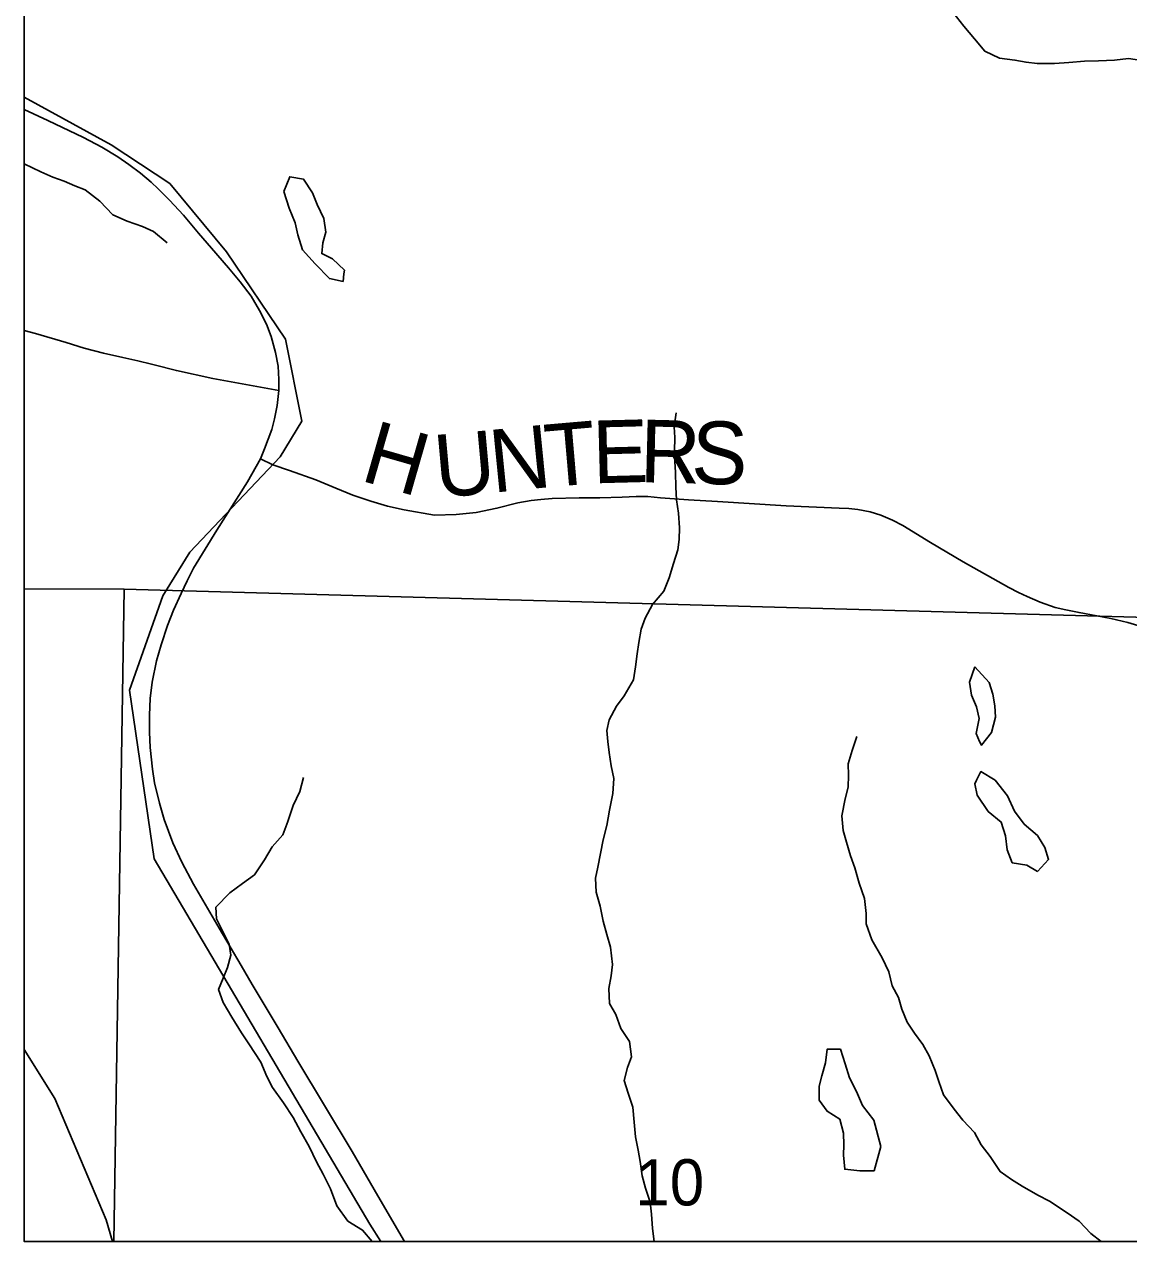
# Model space of a CAD drawing. Extents: x 0 to 34, y 0 to 22.
# Drawn here: x 1.631 to 2.631, y 14.573 to 15.676 of the extents above; entities that cross this region are included whole.
import ezdxf

# ---------------------------------------------------------------- set-up
doc = ezdxf.new("R2010")
doc.units = 0
for name, color, linetype in [('GM_X_Corporation', 7, 'Continuous'), ('GM_X_County_Road', 7, 'Continuous'), ('GM_X_Minor_Lake', 7, 'Continuous'), ('GM_X_Minor_River', 7, 'Continuous'), ('GM_X_Rail_Line', 7, 'Continuous'), ('GM_X_Section_Text', 7, 'Continuous'), ('GM_X_State_Route', 7, 'Continuous'), ('GM_X_Township_Road', 7, 'Continuous'), ('GM_X_Township_Road_Text', 7, 'Continuous'), ('SH_Text', 7, 'Continuous')]:
    doc.layers.add(name, color=color, linetype=linetype)

msp = doc.modelspace()

# ---------------------------------------------------------------- linework, layer by layer
at = {"layer": 'GM_X_Corporation'}
msp.add_lwpolyline([(4.1576, 16.1007), (3.7652, 16.1115), (2.3935, 16.1523), (2.3716, 16.1532), (1.6311, 16.1731), (1.6311, 14.5734), (8.4311, 14.5734)], dxfattribs=at)
for points in [[(1.6311, 16.1731), (1.6311, 14.5734), (3.7221, 14.5734), (3.7347, 15.1105), (3.7348, 15.1121), (3.7459, 15.4785), (3.7461, 15.4826), (3.7495, 15.5967), (3.7652, 16.1115), (2.3935, 16.1523), (2.3716, 16.1532)], [(1.6311, 15.1646), (1.6311, 14.5734), (1.7122, 14.5734), (1.7214, 15.1643)], [(1.7122, 14.5734), (2.7191, 14.5734), (2.725, 15.1366), (1.7214, 15.1643)]]:
    msp.add_lwpolyline(points, close=True, dxfattribs=at)
at = {"layer": 'GM_X_County_Road'}
msp.add_lwpolyline([(1.711, 14.5734), (1.7053, 14.5933), (1.6588, 14.7031), (1.6311, 14.7473)], dxfattribs=at)
at = {"layer": 'GM_X_Minor_Lake'}
for points in [[(1.9205, 15.4498), (1.9209, 15.4533), (1.9103, 15.4634), (1.9004, 15.4683), (1.9015, 15.4781), (1.904, 15.4876), (1.9024, 15.5001), (1.8963, 15.5126), (1.8921, 15.5232), (1.884, 15.5356), (1.8715, 15.5378), (1.866, 15.5245)], [(1.866, 15.5245), (1.871, 15.5094), (1.8764, 15.4962), (1.8787, 15.4852), (1.883, 15.4716), (1.8944, 15.4588), (1.9074, 15.4456), (1.9198, 15.443), (1.9205, 15.4498)], [(2.4919, 15.0939), (2.487, 15.0802), (2.4889, 15.0684), (2.4935, 15.0578), (2.4958, 15.0472), (2.4932, 15.0336), (2.4962, 15.0265)], [(2.4962, 15.0265), (2.4978, 15.023), (2.5068, 15.0344), (2.5106, 15.0484), (2.5101, 15.0587), (2.5082, 15.0693), (2.5048, 15.0799), (2.4919, 15.0939)], [(2.5485, 14.9086), (2.5586, 14.9196), (2.5552, 14.9303), (2.5487, 14.9412), (2.5366, 14.9514), (2.5278, 14.9632), (2.5214, 14.9772), (2.5103, 14.9912), (2.4974, 14.9991), (2.4935, 14.9914)], [(2.4935, 14.9914), (2.4918, 14.9881), (2.4941, 14.9778), (2.504, 14.9631), (2.5158, 14.9533), (2.5196, 14.9408), (2.5211, 14.9282), (2.5257, 14.9165), (2.539, 14.9143), (2.5485, 14.9086)], [(2.4003, 14.6833), (2.3902, 14.6966), (2.3848, 14.7095), (2.3783, 14.7219), (2.3744, 14.7344), (2.3702, 14.7477), (2.3581, 14.7476), (2.3567, 14.7354), (2.3533, 14.7237), (2.3508, 14.7142), (2.3508, 14.7016), (2.3581, 14.6915), (2.3695, 14.6843), (2.373, 14.6715), (2.3731, 14.6612), (2.3728, 14.6518), (2.374, 14.6389), (2.3876, 14.6375), (2.4007, 14.6375)], [(2.4007, 14.6375), (2.4067, 14.6595), (2.4003, 14.6833)]]:
    msp.add_lwpolyline(points, dxfattribs=at)
at = {"layer": 'GM_X_Minor_River'}
for points in [[(2.6432, 15.643), (2.6311, 15.6449), (2.6182, 15.6433), (2.6038, 15.6429), (2.5913, 15.6425), (2.5769, 15.6413), (2.5641, 15.6405), (2.5482, 15.6404), (2.5383, 15.6415), (2.5281, 15.6434), (2.5141, 15.6452), (2.5008, 15.6516), (2.4917, 15.6626), (2.4818, 15.6743), (2.4719, 15.6868)], [(1.6311, 15.5494), (1.646, 15.5423), (1.657, 15.5375), (1.6673, 15.5338), (1.6768, 15.5297), (1.6863, 15.526), (1.6996, 15.5158), (1.7114, 15.5034), (1.7243, 15.4975), (1.738, 15.4927), (1.7482, 15.4882), (1.7604, 15.4781)], [(2.2015, 14.5734), (2.2, 14.5853), (2.1992, 14.5982), (2.1979, 14.6092), (2.1937, 14.6217), (2.1906, 14.633), (2.1889, 14.6459), (2.187, 14.6561), (2.1846, 14.6682), (2.1834, 14.6815), (2.1821, 14.6951), (2.1779, 14.708), (2.1744, 14.7194), (2.1773, 14.7311), (2.181, 14.7407), (2.179, 14.7547), (2.1713, 14.7664), (2.1667, 14.7792), (2.1609, 14.789), (2.1605, 14.8027), (2.1626, 14.8141), (2.1637, 14.8243), (2.162, 14.8402), (2.1586, 14.8516), (2.1554, 14.8637), (2.1527, 14.8773), (2.1488, 14.8898), (2.1483, 14.9027), (2.1505, 14.9126), (2.1552, 14.9372), (2.1585, 14.9502), (2.1611, 14.9642), (2.164, 14.9794), (2.165, 14.9927), (2.1626, 15.0044), (2.1607, 15.0165), (2.1594, 15.0264), (2.1586, 15.0362), (2.1608, 15.0461), (2.1675, 15.0583), (2.1742, 15.0678), (2.1828, 15.0823), (2.1846, 15.0941), (2.1861, 15.1058), (2.1875, 15.1161), (2.1897, 15.1282), (2.1934, 15.1381), (2.2001, 15.1503), (2.2102, 15.1625), (2.215, 15.1747), (2.2191, 15.1876), (2.2228, 15.1998), (2.2242, 15.2093), (2.2245, 15.2199), (2.2236, 15.2332), (2.2217, 15.2453), (2.2212, 15.2567), (2.2207, 15.2699), (2.2203, 15.2798), (2.2198, 15.2892), (2.2201, 15.3018), (2.2196, 15.3112), (2.2214, 15.3241)], [(2.3987, 14.8467), (2.3935, 14.8611), (2.3934, 14.8706), (2.3918, 14.8842), (2.3871, 14.8982), (2.3832, 14.9118), (2.3794, 14.9228), (2.3755, 14.9353), (2.3727, 14.9459), (2.3715, 14.9591), (2.3744, 14.9743), (2.377, 14.9849), (2.3773, 14.9959), (2.3772, 15.0062), (2.3809, 15.0183), (2.3849, 15.0309)], [(1.9461, 14.5734), (1.9374, 14.5839), (1.9241, 14.5918), (1.9142, 14.6057), (1.9084, 14.6212), (1.9018, 14.6344), (1.8957, 14.6458), (1.8891, 14.6597), (1.8815, 14.673), (1.8745, 14.6858), (1.8657, 14.699), (1.8558, 14.7129), (1.8508, 14.7231), (1.8454, 14.736), (1.8343, 14.7526), (1.8278, 14.7624), (1.819, 14.7767), (1.8113, 14.7899), (1.807, 14.8017), (1.8111, 14.8119), (1.8152, 14.8218), (1.8181, 14.8328), (1.8165, 14.8427), (1.8119, 14.8525), (1.805, 14.8657), (1.8045, 14.8763), (1.8173, 14.8893), (1.8286, 14.8978), (1.8395, 14.9055), (1.8485, 14.9192), (1.8556, 14.931), (1.8653, 14.9417), (1.8698, 14.9539), (1.8746, 14.9683), (1.8805, 14.9812), (1.8838, 14.9938)], [(2.6064, 14.5734), (2.6063, 14.5735), (2.5968, 14.5807), (2.5862, 14.592), (2.5755, 14.5996), (2.5596, 14.6102), (2.549, 14.6154), (2.5346, 14.6237), (2.5251, 14.6298), (2.5148, 14.6369), (2.5057, 14.6506), (2.4977, 14.6611), (2.4916, 14.6721), (2.481, 14.6835), (2.473, 14.6933), (2.4635, 14.7065), (2.4593, 14.7183), (2.4559, 14.7285), (2.4505, 14.7418), (2.4448, 14.752), (2.4372, 14.7622), (2.4307, 14.7721), (2.4258, 14.7838), (2.4227, 14.7944), (2.417, 14.805), (2.4139, 14.8179), (2.4078, 14.8304), (2.3987, 14.8467)]]:
    msp.add_lwpolyline(points, dxfattribs=at)
at = {"layer": 'GM_X_Rail_Line'}
msp.add_lwpolyline([(1.954, 14.5734), (1.944, 14.5891), (1.7486, 14.9201), (1.7264, 15.0728), (1.7565, 15.1584), (1.7809, 15.1978), (1.8629, 15.2843), (1.8824, 15.3166), (1.8675, 15.3908), (1.8141, 15.4698), (1.7628, 15.5318), (1.7096, 15.5667), (1.6311, 15.6098)], dxfattribs=at)
at = {"layer": 'GM_X_State_Route'}
for points in [[(1.6311, 15.5988), (1.6525, 15.5889), (1.6847, 15.5734), (1.7014, 15.5646), (1.7158, 15.5558), (1.7257, 15.549), (1.7363, 15.541), (1.7461, 15.5328), (1.7523, 15.527), (1.7627, 15.5166), (1.7752, 15.5029), (1.7889, 15.4866), (1.8005, 15.4731), (1.8159, 15.4552), (1.8267, 15.4427), (1.8365, 15.4296), (1.8441, 15.4168), (1.8503, 15.4042), (1.8545, 15.393), (1.8585, 15.3787), (1.8609, 15.3664), (1.8617, 15.3543), (1.8615, 15.3441)], [(1.8615, 15.3441), (1.8601, 15.3305), (1.8578, 15.3185), (1.8552, 15.309), (1.8487, 15.2913), (1.845, 15.2823)], [(1.845, 15.2823), (1.841, 15.2753), (1.8331, 15.2616), (1.8054, 15.2177), (1.7843, 15.1832), (1.7785, 15.1718), (1.773, 15.1604), (1.7662, 15.1454), (1.7607, 15.1315), (1.7549, 15.114), (1.7508, 15.0995), (1.7469, 15.08), (1.7451, 15.0654), (1.7446, 15.0502), (1.7445, 15.0347), (1.745, 15.021), (1.7472, 15.0013), (1.749, 14.9888), (1.7534, 14.9704), (1.7576, 14.9557), (1.7655, 14.9347), (1.7736, 14.9172), (1.7843, 14.8971), (1.8076, 14.8574), (1.8274, 14.8235), (1.8374, 14.8064), (1.861, 14.767), (1.8788, 14.737), (1.9279, 14.6551), (1.9513, 14.6148), (1.9755, 14.5734)]]:
    msp.add_lwpolyline(points, dxfattribs=at)
at = {"layer": 'GM_X_Township_Road'}
for points in [[(1.7486, 15.3674), (1.7463, 15.368), (1.7338, 15.3711), (1.7202, 15.3742), (1.7029, 15.3779), (1.6854, 15.3825), (1.6691, 15.3876), (1.6412, 15.396), (1.6311, 15.3987)], [(1.8615, 15.3441), (1.8017, 15.3552), (1.7688, 15.3623), (1.7486, 15.3674)], [(1.845, 15.2823), (1.8487, 15.2913), (1.8552, 15.309), (1.8578, 15.3185), (1.8601, 15.3305), (1.8615, 15.3441)], [(2.6477, 15.1291), (2.6305, 15.1342), (2.615, 15.1377), (2.6022, 15.1403), (2.5863, 15.1431), (2.5744, 15.1455), (2.5647, 15.1478), (2.5511, 15.1525), (2.5392, 15.1576), (2.5313, 15.1613), (2.5227, 15.1658), (2.4812, 15.1892), (2.4516, 15.2067), (2.4265, 15.2221), (2.4173, 15.2269), (2.4067, 15.2312), (2.397, 15.2343), (2.3859, 15.2364), (2.3777, 15.2374), (2.3691, 15.2378), (2.3209, 15.2397), (2.2588, 15.2436), (2.2326, 15.2452), (2.2071, 15.2471), (2.1956, 15.2481), (2.1851, 15.2482), (2.1725, 15.2477), (2.1522, 15.2471), (2.1335, 15.247), (2.1091, 15.2463), (2.0987, 15.2456), (2.0901, 15.2446), (2.0779, 15.2424), (2.059, 15.2376), (2.0404, 15.2338), (2.0221, 15.2318), (2.0026, 15.2312), (1.975, 15.2362), (1.9601, 15.2396), (1.9448, 15.2439), (1.9285, 15.2495), (1.9133, 15.2559), (1.8952, 15.2634), (1.8713, 15.2717), (1.8561, 15.277), (1.845, 15.2823)]]:
    msp.add_lwpolyline(points, dxfattribs=at)
at = {"layer": 'SH_Text'}
for p, q in [((1.6311, 14.5734), (1.6311, 21.3734)), ((8.4311, 14.5734), (1.6311, 14.5734))]:
    msp.add_line(p, q, dxfattribs=at)

# ---------------------------------------------------------------- texts
at = {"layer": 'GM_X_Section_Text'}
msp.add_text('10', height=0.04186, rotation=0, dxfattribs=at).set_placement((2.1845, 14.6062))
at = {"layer": 'GM_X_Township_Road_Text'}
for s, rotation, p in [('H', 343.918, (1.9341, 15.2631)), ('N', 5.6715, (2.0552, 15.2516)), ('T', 4.9387, (2.1048, 15.2565)), ('E', 1.4915, (2.1462, 15.2601)), ('R', 358.6104, (2.188, 15.2612)), ('S', 358.3416, (2.2346, 15.2601)), ('U', 5.1631, (2.0049, 15.247))]:
    msp.add_text(s, height=0.0568, rotation=rotation, dxfattribs=at).set_placement(p)

doc.saveas('drawing.dxf')
